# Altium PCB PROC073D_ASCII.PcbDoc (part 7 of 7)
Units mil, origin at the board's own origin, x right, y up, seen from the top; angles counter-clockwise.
Board outline 2165.35 x 2695.12 mil, 8 copper layers (Top Layer, L2_GND, L3_SIGNAL 1, L4_SIGNAL 2, L5_SIGNAL 3, L6_SIGNAL 4, L7_GND, Bottom Layer), stack 56.1 mil thick; 414 components, 319 nets, 1353 pads, 1669 vias.
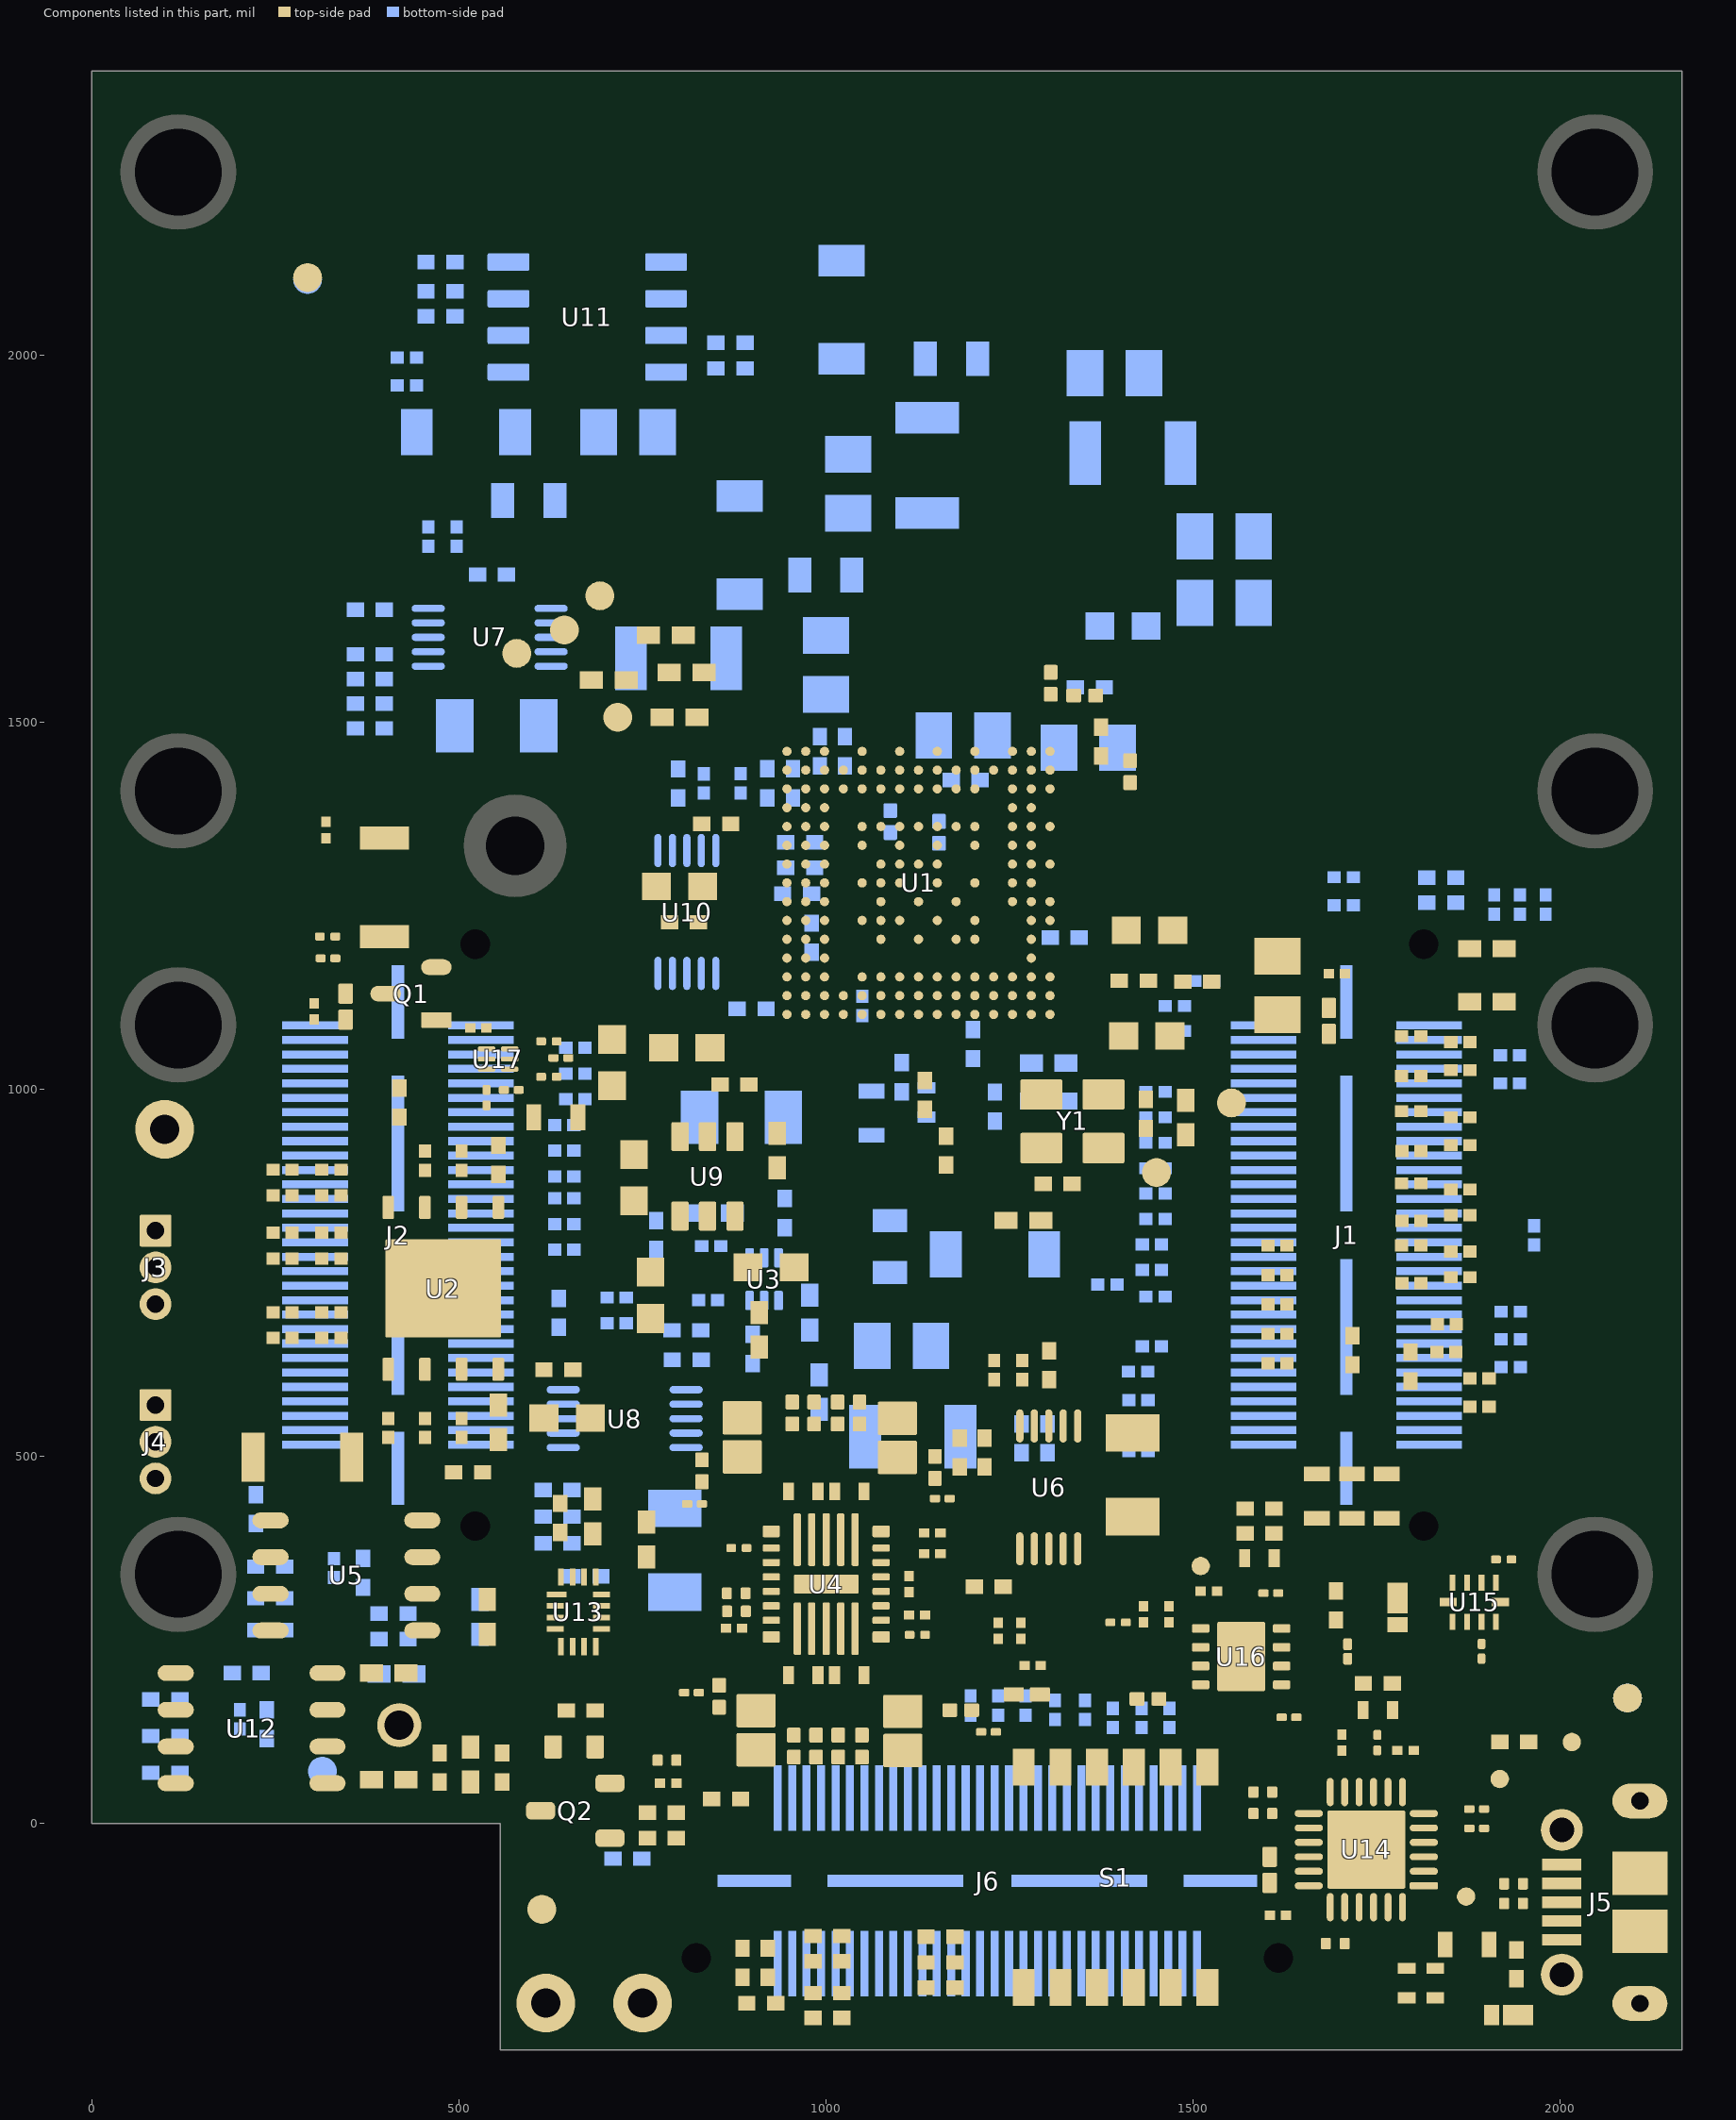
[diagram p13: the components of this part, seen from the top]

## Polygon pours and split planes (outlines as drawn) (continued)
GND on Bottom Layer "GND_L08_P43708" (solid, remove dead copper, pour order 43708): 975.14,521.11 988.65,507.61 988.65,471.77 994.8,465.62 1006.27,465.62 1025.86,485.21 1025.86,527.91 1006.22,547.55 1006.22,578.24 1002.3,582.17 980.16,582.17 975.14,577.15
GND on Bottom Layer "GND_L08_P43707" (solid, remove dead copper, pour order 43707): 1020.69,190.86 987.66,190.86 970.67,173.88 970.67,130.44 978.32,122.79 1021.07,122.79 1033.19,134.91 1033.19,178.36
VCC_3V3 on Bottom Layer "VCC_3V3_L08_P43705" (solid, remove dead copper, pour order 43705): 465.74,1033.13 458.09,1025.48 458.09,1009.78 465.84,1002.03 575.16,1002.03 575.16,1033.13
CONN_5V on Bottom Layer "CONN_5V_L08_P43704" (solid, remove dead copper, pour order 43704): 668.21,-84.13 681.85,-84.12 686.38,-79.59 686.38,-71.25 696.78,-60.85 720,-60.85 722.36,-58.49 722.36,-32.62 717.86,-28.12 689.04,-28.12 681.58,-20.66 678.03,-17.11 661.3,-17.11 655.38,-23.02 655.38,-71.3
PMIC_1V2 on Bottom Layer "PMIC_1V2_L08_P43702" (solid, remove dead copper, pour order 43702): 1134.07,211.23 1134.07,235.63 1110.26,259.43 1086.92,259.43 1076.28,248.79 1076.28,231.35 1106.13,201.5 1124.34,201.5
5V_IN on Bottom Layer "5V_IN_L08_P43699" (solid, remove dead copper, pour order 43699): 1079.81,216.18 1089.5,206.49 1095.69,200.05 1095.69,191.21 1084.57,180.09 1057.11,180.09 1051.43,185.77 1051.43,216.88 1060.25,225.7 1070.29,225.7
PMIC_1V0 on Bottom Layer "PMIC_1V0_L08_P43698" (solid, remove dead copper, pour order 43698): 876.66,448.22 876.66,420.56 896.55,400.67 911.73,400.67 919.69,408.62 919.69,420.01 899.93,439.77 899.93,445.6 889.72,455.8 884.25,455.81
PMIC_3V3 on Bottom Layer "PMIC_3V3_L08_P43701" (solid, remove dead copper, pour order 43701): 912.52,36.44 920.36,44.28 920.36,73.1 914.77,78.7 886.7,78.7 879.71,71.7 879.71,42.95 886.22,36.44
5V_IN on Bottom Layer "5V_IN_L08_P43697" (solid, remove dead copper, pour order 43697): 935.79,469.23 913.45,469.23 906.78,462.56 906.78,441.82 922.01,426.59 934.29,426.59 943.38,435.68 943.38,461.65
5V_IN on Bottom Layer "5V_IN_L08_P43696" (solid, remove dead copper, pour order 43696): 1065.52,469.88 1089.92,469.88 1094.53,465.26 1094.53,446.19 1089.35,441 1079.36,431.02 1060.29,431.02 1056.16,435.15 1056.16,460.52
5V_IN on Bottom Layer "5V_IN_L08_P43695" (solid, remove dead copper, pour order 43695): 939.63,221.08 922.83,221.08 912.64,210.9 907.24,205.5 907.24,188.9 913.3,182.84 937.84,182.84 946.5,191.5 946.5,214.21
no net on Bottom Layer "NONET_L08_P43693" (solid, remove dead copper, pour order 43693): 1569.79,-6.89
no net on Bottom Layer "NONET_L08_P43694" (solid, remove dead copper, pour order 43694): 804.19,1139.15
no net on Bottom Solder "RADAR_1V8_L01_P-001" (solid, pour order 43747): 48 vertices, not listed, extent 1068,1195.43 1955,2232.3
CONN_5V on L4_SIGNAL 2 "CONN_5V_L04_P43676" (solid, remove dead copper, pour order 43676): 22 vertices, not listed, extent 1388.84,-101.66 1860.72,535.27
VCC_LD_SW_3V3 on L4_SIGNAL 2 "VCC_LD_SW_3V3_L04_P43678" (solid, remove dead copper, pour order 43678): 826.61,990.49 837.44,979.66 930.65,979.66 990.05,920.27 990.05,583.83 942.18,535.96 942.18,502.93 925.77,486.52 865.94,486.52 813.5,538.95 713.54,538.95 706.94,545.55 706.94,982.46 714.97,990.49
GND on L4_SIGNAL 2 "GND_L04_P43683" (solid, remove dead copper, pour order 43683): 78 vertices, not listed, extent 273.62,-307.72 1388.71,1117.7
PMIC_1V2 on L4_SIGNAL 2 "PMIC_1V2_L04_P43677" (solid, remove dead copper, pour order 43677): 38 vertices, not listed, extent 678.98,78.46 1244.86,516.83
RADAR_3V3 on L4_SIGNAL 2 "RADAR_3V3_L04_P43684" (solid, remove dead copper, pour order 43684): 18 vertices, not listed, extent 788.39,1067.34 2037.57,1708.68
5V_IN on L4_SIGNAL 2 "5V_IN_L04_P43682" (solid, remove dead copper, pour order 43682): 29 vertices, not listed, extent 1546.44,-281.93 1963.86,284.3
CB_PMIC_1V0 on L4_SIGNAL 2 "CB_PMIC_1V0_L04_P43680" (solid, remove dead copper, pour order 43680): 434.47,1775.47 560.43,1775.47 647.64,1862.68 767.58,1862.68 828.79,1801.47 828.79,1543.27 721.27,1435.76 600.53,1435.76 560.34,1395.57 416.07,1395.57 400.94,1410.7 400.94,1741.94
5V_IN on L4_SIGNAL 2 "5V_IN_L04_P43681" (solid, remove dead copper, pour order 43681): 27 vertices, not listed, extent 133.29,-286.19 887.24,280.97
PMIC_1V8 on L4_SIGNAL 2 "PMIC_1V8_L04_P43679" (solid, remove dead copper, pour order 43679): 1248.09,667.01 1444.87,470.23 1444.87,387.29 1444.87,343.72 1356.02,254.87 1168.38,254.87 1037.34,385.92 980.94,385.92 948.61,418.25 948.61,533.17 992.02,576.57 992.02,636.86 1022.17,667.01
VCC_3V3 on L4_SIGNAL 2 "VCC_3V3_L04_P43675" (solid, remove dead copper, pour order 43675): 28 vertices, not listed, extent 820.26,-10.94 1308.08,317.12
RADAR_1V2 on L4_SIGNAL 2 "RADAR_1V2_L04_P43674" (solid, remove dead copper, pour order 43674): 1013.51,974.4 1116.92,974.4 1161.23,1018.71 1161.23,1052.08 1161.23,1069.81 1139.09,1091.95 985.01,1091.95 948.19,1128.77 851.6,1128.77 814.78,1091.94 814.78,1027.31 867.69,974.4
PMIC_3V3 on L4_SIGNAL 2 "PMIC_3V3_L04_P43673" (solid, remove dead copper, pour order 43673): 17 vertices, not listed, extent 845.88,35.77 958.85,254.27
CB_PMIC_1V0 on L6_SIGNAL 4 "CB_PMIC_1V0_L06_P43692" (solid, remove dead copper, pour order 43692): 23 vertices, not listed, extent 372.31,440.16 1780.59,2062.92
CONN_5V on L6_SIGNAL 4 "CONN_5V_L06_P43687" (solid, remove dead copper, pour order 43687): 23 vertices, not listed, extent 705.14,-283.5 1414.33,358.14
PMICOUT_3V3 on L6_SIGNAL 4 "PMICOUT_3V3_L06_P43689" (solid, remove dead copper, pour order 43689): 1788.28,475.23 1866.94,553.89 2079.57,553.89 2157.3,476.16 2157.3,-7.63 2057.41,-107.52 1681.52,-107.52 1635.4,-61.4 1635.4,109.01 1698.06,171.67 1788.28,261.89
5V_IN on L6_SIGNAL 4 "5V_IN_L06_P43691" (solid, remove dead copper, pour order 43691): 30 vertices, not listed, extent 29.98,-283.8 1095.63,1210.97
PMIC_1V0 on L6_SIGNAL 4 "PMIC_1V0_L06_P43690" (solid, remove dead copper, pour order 43690): 34 vertices, not listed, extent 427.96,515.02 978.35,1613.68
RADAR_1V8 on L6_SIGNAL 4 "RADAR_1V8_L06_P43688" (solid, remove dead copper, pour order 43688): 23 vertices, not listed, extent 883.8,629.93 1255.75,1534.83
PMICVIO_3V3 on L6_SIGNAL 4 "PMICVIO_3V3_L06_P43686" (solid, remove dead copper, pour order 43686): 17 vertices, not listed, extent 772.65,219.56 1190.94,488.5
VCC_3V3 on L6_SIGNAL 4 "VCC_3V3_L06_P43685" (solid, remove dead copper, pour order 43685): 347.07,1482.73 412,1417.8 412,1394.41 420.32,1386.08 420.32,1173.19 502.41,1091.11 502.41,1027.03 476.08,1000.7 376.25,1000.7 347.25,1029.7 347.25,1175.35 235.53,1287.07 235.53,1459.64 258.62,1482.73
GND on L2_GND "GND_L02_P226" (hatched 90Degree grid 5 track 8, remove dead copper, pour order 43649): 34.96,35.8 583.08,35.8 583.08,-276.77 701.29,-276.63 2135,-276.63 2135.01,2361.43 34.96,2361.42
GND on L7_GND "TOP-No Net 1" (solid, remove dead copper, pour order 43672): 0,172.07 0,39.66 28.97,10.69 544.02,10.69 575.91,-21.2 575.91,-276.57 607.69,-308.34 1082.68,-308.34 2165.35,-308.34 2165.35,2368.81 0,2368.81

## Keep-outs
L2_GND:
  circle w1: c1074.8,1434.59 r7.87
  circle w1: c1177.16,1434.59 r7.87
  circle w1: c1125.98,1434.59 r7.87
  circle w1: c1279.53,1281.05 r7.87
  circle w1: c1279.52,1383.41 r7.87
  circle w1: c1279.52,1332.23 r7.87
  circle w1: c522.48,1197.95 r32
  circle w1: c1023.62,1434.59 r7.87
L3_SIGNAL 1:
  circle w1: c522.48,1197.95 r32
L5_SIGNAL 3:
  circle w1: c522.48,1197.95 r30
L7_GND:
  circle w1: c522.48,1196.95 r32
Bottom Layer:
  circle w1: c522.48,1197.95 r27.7
Keep-Out Layer:
  circle w1: c823.48,-182.98 r32
  circle w1: c1616,-182.98 r32
  circle w1: c522.48,1197.43 r32
  circle w1: c1813.86,1197.69 r32
  circle w1: c1813.86,405.17 r31
  circle w1: c522.48,404.91 r32
  lines w10: -5,-5 551.54,-5 551.54,-313.34 2170.35,-313.34 2170.35,2391.78 -5,2391.78 -5,-5
  text ".Layer_Name" at -423,-1637.06 h60

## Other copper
Top Layer:
  text ".Layer_Name" at -423,-1637.06 h60
L2_GND:
  text ".Layer_Name" at -423,-1637.06 h60
L3_SIGNAL 1:
  text ".Layer_Name" at -423,-1637.06 h60
L5_SIGNAL 3:
  text ".Layer_Name" at -423,-1637.06 h60
L7_GND:
  text ".Layer_Name" at -423,-1637.06 h60
L4_SIGNAL 2:
  text ".Layer_Name" at -423,-1637.06 h60
L6_SIGNAL 4:
  text ".Layer_Name" at -423,-1637.06 h60
Bottom Layer:
  text ".Layer_Name" at -423,-1637.06 h60

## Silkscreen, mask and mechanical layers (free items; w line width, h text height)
Top Overlay:
  circle w6: c486.63,1402.09 r30
  circle w10: c1851.26,-90.22 r4.23
  rectangle: 1334.64,1437.44 1353.4,1473.8
  lines w6: 187.08,648.37 187.08,663.46 216.47,692.85 ; 203.5,897.76 198.92,893.18 198.92,786.66 214.76,770.82 ; 359.1,630.7 371.21,642.81 371.21,683.3 364.91,689.6 ; 479.38,497.57 497.97,497.57 500.7,500.3 ; 627.98,1907.74 627.98,1754.26 696.21,1754.26 ; 648.31,1016.63 654.42,1016.63 664.22,1026.43 664.22,1159.01 ; 657.67,-196.22 706.66,-147.23 ; 713.82,1771.85 713.82,1906.52 ; 726.18,1864.99 731.82,1859.36 731.82,1665.75 746.37,1651.2 ; 895.08,-55.65 923.22,-83.79 923.22,-145.7 ; 1024.91,-22.27 1033.92,-31.29 1033.92,-132.02 ; 1073.36,200.77 1098.69,200.77 1106.54,208.62 ; 1151.44,-53.19 1173.87,-75.62 1173.87,-132.25 ; 1164.06,461.56 1194.56,461.56 ; 1432.01,927.8 1432.01,910.65 1398.09,876.73 ; 1432.32,236.29 1432.32,257.47 ; 1460.96,324.94 1464.36,321.55 1464.36,313.48 ; 1486.06,380.76 1486.06,342.13 1491.66,336.53 ; 1552.22,441.76 1552.22,357.83 1555.67,354.37 ; 1622.2,14.4 1630.02,22.22 1630.02,38.52 ; 1636.74,-105.56 1651.26,-120.08 1651.26,-206.52 1647.26,-210.52 ; 1742.66,1043.42 1742.66,1048.18 1754.79,1060.31 ; 1750.24,-194.69 1765.99,-178.94 1810.5,-178.94 1813.92,-182.36 ; 1398.09,876.73 1408.09,876.73 1398.09,886.73 1398.09,876.73
  text "PROC073    REV D" at 498.37,1516.31 h45 r90
  text "C" at 1267.07,1500.27 h50
  text "C" at 473.15,1386 h50
  text ".Layer_Name" at -423,-1637.06 h60
Bottom Overlay:
  circle w6: c1519.56,1949.66 r30
  circle w6: c696.91,1476.87 r30
  circle w6: c667.74,1135.94 r30
  circle w6: c306.34,2022.03 r30
  lines w6: 190.46,462.35 196.84,455.97 196.84,388.99 210.64,375.18 ; 230.93,1048.86 249.25,1067.18 ; 260.27,1681.28 367.53,1681.28 367.53,1974.51 ; 603.52,363 603.52,211.13 609.81,204.84 ; 618.56,758.7 677.15,758.7 677.71,759.26 677.71,954.38 698.6,975.27 698.6,1081.8 638.79,1081.8 ; 722.34,1454.6 734.1,1442.84 775.46,1442.84 ; 779.7,1385.25 779.7,1456.44 931.48,1456.44 966.88,1491.84 975.56,1491.84 ; 849.15,668.59 869.41,648.34 869.41,604.48 ; 911.78,1303.56 925.28,1303.56 ; 915.72,796.02 915.72,863.46 ; 997.88,1408.3 1062.42,1408.3 1073.68,1419.57 1073.68,1469.29 1050.83,1492.14 1047.37,1492.14 ; 1457.62,2032.88 1457.62,2102.66 1701.27,2102.66 1701.27,2021.45 1701.27,1988.75 1590.42,1988.75 ; 1864.28,1231.5 1864.28,1223.35 1900.82,1186.81 ; 1872.86,515.65 1888.58,499.93 1888.54,457.99
  text "A" at 323.27,2006.33 h50
  text "B" at 1531.31,1932.8 h50
  text "B" at 708.67,1460 h50
  text "5V_IN" at 480.84,1240.74 h45
  text "A" at 684.67,1120.24 h50
  text "60" at 1938.04,1117.62 h60
  text "5V_IN" at 220.8,1086.19 h50 r270
  text "VPP_1P7" at 219.08,892.8 h40 r270
  text "1V8" at 1546.29,581.12 h40
  text "1V2" at 1546.95,549.97 h40
  text "3V3" at 1939.64,530.67 h40
  text "1V0" at 1544.85,512.29 h40
  text "2" at 589.41,507.23 h40
  text "1" at 228.35,497.9 h40
  text "5V_IN" at 1957.22,422.23 h40
  text "1" at 1549.43,389.07 h60
  text "TEXAS" at 1484.42,350.58 h70
  text "INSTRUMENTS" at 1583.13,294.25 h70
  text ".Layer_Name" at -423,-1637.06 h60
Top Paste:
  text ".Layer_Name" at -423,-1637.06 h60
Bottom Paste:
  text ".Layer_Name" at -423,-1637.06 h60
Top Solder:
  rectangle: 33,2226.43 1975.16,2365.43
  text ".Layer_Name" at -423,-1637.06 h60
  text ".Layer_Name" at -423,-1637.06 h60
Bottom Solder:
  text ".Layer_Name" at -423,-1637.06 h60
Drill Guide:
  text ".Layer_Name" at -423,-1637.06 h60
M1 Board Outline:
  the board outline again, w10
  text ".Layer_Name" at -423,-1637.06 h60
M2 Board Dimensions:
  rectangle: -1000,-1053.57 -875,-928.57
  rectangle: -875,-1178.57 -500,-1053.57
  lines w7: -1000,-1053.57 0,-1053.57 ; -875,-1178.57 -875,-928.57 ; -750,-1178.57 -750,-928.57 ; -500,-1178.57 -500,-928.57 ; -250,-1178.57 -250,-928.57 ; -1000,-1178.57 0,-1178.57 0,-928.57 -1000,-928.57 -1000,-1178.57
  text ".Layer_Name" at -434.88,-1635.12 h60
M3 3D STEP Top:
  text ".Layer_Name" at -423,-1637.06 h60
M4 3D STEP Bottom:
  text ".Layer_Name" at -423,-1637.06 h60
M5 Assembly Top:
  lines w10: -1292,-1708.74 5308,-1708.74 ; -1292,-1505.4 5310,-1505.4 ; -1292,-1302.07 -1292,-1912.07 2713,-1912.07 5310,-1912.07 5310,-1302.07 -1291.5,-1302.07 -1291.5,-1912.07 284,-1912.07 ; 1173,-1912.07 1173,-1302.07 ; 2440,-1505.4 2440,-1302.07 ; 3280,-1505.4 3280,-1302.07 ; 3902,-1918.57 3902,-1715.74
  text "COMPONENTS MARKED 'DNP' SHOULD NOT BE POPULATED." at 153.5,-1097.07 h60
  text "ASSEMBLY VARIANT:" at 153,-1212.57 h60
  text ".VariantName" at 1189,-1212.57 h60
  text "PCB VIEWED FROM TOP SIDE" at -1228.5,-1434.24 h60
  text "BOARD #:" at 1248,-1434.24 h60
  text ".PRJ_Number" at 1793.5,-1434.24 h60
  text "REV:" at 2638,-1434.24 h60
  text ".PCB_Rev" at 2929.5,-1434.24 h60
  text "SVN REV:" at 3476,-1434.24 h60
  text ".VersionControl_RevNumber" at 3982,-1434.24 h60
  text "Assembly Layer Top" at -433,-1633.57 h60
  text "TID #:" at 1248,-1637.57 h60
  text ".TID" at 1793.5,-1637.57 h60
  text "PLOT NAME =" at -1228.5,-1842.91 h60
  text ".plot_File_Name" at -423,-1842.91 h60
  text "GENERATED    :" at 1250,-1842.91 h60
  text ".Print_Date" at 2119.5,-1842.91 h60
  text ".Print_Time" at 2848.5,-1842.91 h60
  text "TEXAS INSTRUMENTS" at 4113,-1842.91 h60
M6 Assembly Bottom:
  lines w6: 705,946.43 705,1086.43 ; 786.98,859.14 791.01,855.11 791.01,805.11 810.46,785.66 810.46,792.86 802.41,784.81 809.61,784.81 ; 833.84,1452.2 833.84,1469.69 ; 1770.26,1355.04 1770.26,1297.39 1798.64,1269 1798.64,1278.88 1788.68,1268.91 1796.09,1268.91 ; 705,1086.43 714.25,1077.18 695.75,1077.18 705,1086.43
  lines w10: -1292.5,-1505.9 5309.5,-1505.9 ; -1290.5,-1709.24 5309.5,-1709.24 ; 115.5,-1919.07 115.5,-1716.24 ; 737.5,-1505.9 737.5,-1302.57 ; 1577.5,-1505.9 1577.5,-1302.57 ; 2844.5,-1912.57 2844.5,-1302.57 ; 3733.5,-1912.57 5309,-1912.57 5309,-1302.57 -1292.5,-1302.57 -1292.5,-1912.57 1304.5,-1912.57 5309.5,-1912.57 5309.5,-1302.57
  text "59" at 350,1086.43 h45
  text "60" at 530.04,1086.86 h45
  text "59" at 1636,1086.86 h45
  text "60" at 1821.54,1086.86 h45
  text "1" at 325,496.43 h45
  text "2" at 525,496.43 h45
  text "1" at 1611,486.43 h45
  text "2" at 1822,486.43 h45
  text "COMPONENTS MARKED 'DNP' SHOULD NOT BE POPULATED." at 5102,-1096.57 h60
  text ".VariantName" at 4058,-1212.57 h60
  text "ASSEMBLY VARIANT:" at 5097,-1212.57 h60
  text ".VersionControl_RevNumber" at 35.5,-1434.74 h60
  text "SVN REV:" at 541.5,-1434.74 h60
  text ".PCB_Rev" at 1088,-1434.74 h60
  text "REV:" at 1379.5,-1434.74 h60
  text ".PRJ_Number" at 2224,-1434.74 h60
  text "BOARD #:" at 2769.5,-1434.74 h60
  text "PCB VIEWED FROM BOTTOM SIDE" at 5246,-1434.74 h60
  text "Assembly Bottom Layer" at 4885,-1623.57 h60
  text ".TID" at 2224,-1638.07 h60
  text "TID #:" at 2769.5,-1638.07 h60
  text "TEXAS INSTRUMENTS" at -95.5,-1843.41 h60
  text ".Print_Time" at 1169,-1843.41 h60
  text ".Print_Date" at 1898,-1843.41 h60
  text "GENERATED    :" at 2767.5,-1843.41 h60
  text ".plot_File_Name" at 4440.5,-1843.41 h60
  text "PLOT NAME =" at 5246,-1843.41 h60
M7 LPKF Text Top:
  lines w2: 1007.88,1434.59 1039.36,1434.59 ; 1015.75,1434.59 1031.49,1434.59 ; 1023.62,1418.85 1023.62,1450.33 ; 1023.62,1426.72 1023.62,1442.46
M9 Title Sheet:
  lines w10: -1491.5,262.93 -1291.5,262.93 ; -1491.5,2637.93 -1291.5,2637.93 ; -1491.5,5012.93 -1291.5,5012.93 ; 1008.5,-2112.07 1008.5,-1912.07 ; 1008.5,7187.93 1008.5,7387.93 ; 3508.5,-2112.07 3508.5,-1912.07 ; 3508.5,7187.93 3508.5,7387.93 ; 5321,-1912.07 5321,-1302.07 10303.5,-1302.07 ; 6008.5,-2112.07 6008.5,-1912.07 ; 6008.5,7187.93 6008.5,7387.93 ; 8508.5,-2112.07 8508.5,-1912.07 ; 8508.5,7187.93 8508.5,7387.93 ; 10303.5,-1912.07 10303.5,-1302.07 ; 10303.5,-1602.07 13303.5,-1602.07 ; 10303.5,-1002.07 13303.5,-1002.07 ; 10304.5,-408.07 13304.5,-408.07 ; 11008.5,-2112.07 11008.5,-1912.07 ; 11008.5,7187.93 11008.5,7387.93 ; 11808.5,-1902.07 11808.5,-1302.07 ; 13303.5,-1302.07 10303.5,-1302.07 ; 13303.5,-702.07 10303.5,-702.07 ; 13308.5,-712.07 13308.5,-1912.07 ; 13308.5,92.43 10304.5,92.43 10303.5,92.43 10303.5,-408.07 10303.5,-702.07 ; 13308.5,262.93 13508.5,262.93 ; 13308.5,2637.93 13508.5,2637.93 ; 13308.5,5012.93 13508.5,5012.93 ; 10303.5,-1302.07 10303.5,-702.07 ; 13308.5,-1912.07 13308.5,7187.93 -1291.5,7187.93 -1291.5,-1912.07 13308.5,-1912.07 ; -1491.5,-2112.07 -1491.5,7387.93 13508.5,7387.93 13508.5,-2112.07 -1491.5,-2112.07
  text "1" at -260.16,7257.93 h70
  text "2" at 2235.5,7257.93 h70
  text "3" at 4724.84,7257.93 h70
  text "4" at 7231.51,7257.93 h70
  text "5" at 9730.5,7257.93 h70
  text "6" at 12235.5,7257.93 h70
  text "A" at -1416.5,6114.93 h70
  text "A" at 13383.5,6114.93 h70
  text "B" at -1416.5,3734.93 h70
  text "B" at 13383.5,3734.93 h70
  text "C" at -1416.5,1359.93 h70
  text "C" at 13383.5,1359.93 h70
  text "PROJECT TITLE:" at 10343.5,-501.07 h45
  text ".PRJ_Title" at 10393.5,-634.4 h70
  text "DESIGNED FOR:" at 10343.5,-802.07 h45
  text ".PRJ_Customer" at 10393.5,-942.07 h70
  text "D" at -1416.5,-1010.07 h70
  text "D" at 13383.5,-1010.07 h70
  text "FILE NAME:" at 10343.5,-1102.07 h45
  text ".PCB_File_Name_No_Path" at 10393.5,-1222.07 h70
  text "Texas Instruments (TI) and/or its licensors do not warrant the accuracy or completeness of this specification" at 5374,-1383.91 h45
  text "ENGINEER:" at 10343.5,-1392.07 h45
  text "LAYOUT BY:" at 11848.5,-1392.07 h45
  text "or any information contained therein. TI and/or its licensors do not warrant that this design will meet" at 5329.01,-1496.57 h45
  text ".PRJ_Engineer" at 10393.5,-1547.06 h70
  text ".PCB_Layout" at 11899,-1547.06 h70
  text "the specifications, will be suitable for your application or fit for any particular purpose, or will operate in" at 5329.01,-1609.24 h45
  text ".Layer_Name" at -413.7,-1644.05 h60
  text "ALTIUM DESIGNER VERSION:" at 11848.5,-1702.07 h45
  text "an implementation. TI and/or its licensors do not warrant that the design is production worthy. You should" at 5329.01,-1721.91 h45
  text "completely validate and test your design implementation to confirm the system functionality for your application." at 5374,-1834.57 h45
  text ".print_Scale" at 10393.5,-1835.4 h70
  text ".Application_BuildNumber" at 11899,-1835.4 h70
  text "1" at -260.16,-2042.07 h70
  text "2" at 2235.5,-2042.07 h70
  text "3" at 4724.84,-2042.07 h70
  text "4" at 7231.51,-2042.07 h70
  text "5" at 9730.5,-2042.07 h70
  text "WO # : 308145-8143-D" at 12235.5,-2042.07 h70
M10 Fab Notes:
  drawing of 198 lines, arcs and shapes, not listed
  text "DESIGN INFORMATION" at 11382.02,5577.6 h60
  text "MIN. TRACK WIDTH:" at 10737.46,5445.48 h60
  text "4" at 11833.7,5445.48 h60
  text "MIL" at 11988.46,5445.48 h60
  text "3.9" at 11781.69,5328.63 h60
  text "MIN. CLEARANCE:" at 10737.46,5321.35 h60
  text "MIL" at 11988.46,5321.35 h60
  text "MIN. VIA PAD SIZE:" at 10737.46,5197.23 h60
  text "13.77" at 11679,5192.43 h60
  text "MIL" at 12011,5188.43 h60
  text "EXTERNAL" at 12258.6,5069.92 h60
  text "0.0508mm (2.0MIL)" at 11432.46,5067.33 h60
  text "MINIMUM ANNULAR RING" at 10408.23,5059.1 h60
  text "PER" at 10608.23,4948.98 h60
  text "IPC-D-275 CLASS 2 LEVEL C" at 10828.23,4948.97 h60
  text "MIL, HOLES" at 12316.46,4848.5 h60
  text "+/-" at 11924,4839.91 h60
  text "+/-" at 12778,4839.91 h60
  text "REGISTRATION TOLERANCES:" at 10408.23,4838.85 h60
  text "METAL" at 11608,4838.85 h60
  text "5" at 12184.2,4838.85 h60
  text "3" at 13017.2,4838.85 h60
  text "MIL" at 13133.46,4838.85 h60
  text "HOLE SIZE TOLERANCE (UNLESS OTHERWISE SPECIFIED):" at 10408.23,4740.53 h60
  text "+/-" at 12778,4737.66 h60
  text "3" at 13017.2,4736.6 h60
  text "MIL" at 13133.46,4736.6 h60
  text "MATERIAL:" at 10333.46,4598.95 h60
  text "FR-4 High Tg" at 11319.9,4470.42 h60
  text "X" at 12062,4465.43 h60
  text "REFER STACK-UP" at 12562.85,4464.84 h55
  text "FR-408" at 10754.46,4457.92 h60
  text "OTHER" at 12242.46,4457.92 h60
  text "X" at 12233,4317.44 h60
  text "62 MIL (1.6mm) +/-10%" at 11074.56,4314.89 h60
  text "57.37 MIL +/-10%" at 12655,4308.43 h45
  text "THICKNESS:" at 10408.23,4306.67 h60
  text "OTHER" at 12359.46,4306.67 h60
  text "TOLERANCE:" at 10408.23,4168.35 h60
  text "X" at 11256.46,4168.35 h60
  text "ANSI IPC-6012 TYPE 3 CLASS 2" at 11434.48,4168.35 h60
  text "OTHER +/-" at 11434.46,4024.16 h60
  text "BOW & TWIST:" at 10408.23,3878.97 h60
  text "X" at 11256.46,3878.97 h60
  text "ANSI IPC-6012 TYPE 3 CLASS 2" at 11434.48,3878.97 h60
  text "OTHER +/-" at 11434.46,3732.28 h60
  text "DRILLING:" at 10333.46,3601.66 h60
  text "NC_DRILL FILES" at 12094.46,3496.47 h60
  text "REFERENCE:" at 10408.23,3492.53 h60
  text "X" at 11065.46,3492.44 h60
  text "AS SHOWN" at 11243.46,3492.53 h60
  text "X" at 11966.46,3492.53 h60
  text "OTHER" at 12392.46,3350.28 h60
  text "PTH COPPER THICKNESS:" at 10407.91,3346.75 h60
  text "X" at 11547.14,3346.75 h60
  text "20-30 um" at 11675.14,3346.75 h60
  text "BOARD FINISH:" at 10333.46,3199.15 h60
  text "SILKSCREEN:" at 10488.68,3089.03 h60
  text "X" at 11446.46,3089.03 h60
  text "TOP" at 11563.46,3089.03 h60
  text "X" at 11956.46,3089.03 h60
  text "BOTTOM" at 12074.46,3089.03 h60
  text "SILKSCREEN COLOR:" at 10488.68,2933.84 h60
  text "X" at 11445.46,2933.84 h60
  text "WHITE" at 11563.46,2933.84 h60
  text "OTHER" at 12074.46,2933.84 h60
  text "GREEN" at 11694.46,2790.39 h60
  text "X" at 12168.46,2790.39 h60
  text "OTHER" at 12312.46,2790.39 h60
  text "RED" at 12685,2790.39 h60
  text "SOLDER RESIST COLOR:" at 10488.68,2783.52 h60
  text "MATTE" at 11694.46,2636.14 h60
  text "SEMI-GLOSS" at 12312,2635.5 h60
  text "X" at 12168.06,2633.44 h60
  text "IMMERSION GOLD (ENIG)" at 11394.46,2463.37 h60
  text "ENEPIG" at 12732,2456.15 h60
  text "SURFACE FINISH:" at 10333.46,2455.15 h60
  text "IMM. TIN/SILVER OR EQUIV" at 10663,2317.83 h60
  text "X" at 10510,2315.15 h60
  text "OTHER" at 12094.46,2313.89 h60
  text "NOTES:" at 3534.49,2188.99 h60
  text "ARRAY/PANEL:" at 10333.46,2158.52 h60
  text "CUT AND TRIM PER M1 BOARD OUTLINE" at 11394.46,2150.29 h60
  text "N.C. ROUTE" at 11394.46,2014.33 h60
  text "X" at 12082.46,2014.33 h60
  text "V. SCORE" at 12260.46,2014.33 h60
  text "1. VIA'S ON PAD AND BGA PACKAGE AREA SHOULD BE FILLED WITH CONDUCTIVE MATERIAL AND SURFACE SHOULD BE FLAT" at 3563.63,2013.82 h60
  text "BGA AREA VIAS SHOULD BE CAPPED WITH COPPER PLATING TO ENSURE FLAT SURFACE" at 3670.36,1906.67 h60
  text "CERTIFICATION:" at 10333.46,1885.2 h60
  text "MATERIALS AND WORKMANSHIP FOR ALL PCBS" at 11058.46,1885.2 h60
  text "FLATNESS TOLERANCE FOR VIA ON PADS: +0.000 /- 0.001 INCHES ON BOTH SIDES." at 3670.36,1808.09 h60
  text "TO MEET OR EXCEED THE REQUIREMENTS OF:" at 11058.46,1791.14 h60
  text "OTHER THAN BGA AND VIA'S ON THE PAD  VIA FILLING REQUIREMENT CAN BE EXEMPTED" at 3670.36,1698.08 h60
  text "X" at 10695.97,1662.51 h60
  text "ANSI IPC-A-600F CLASS ->" at 10823.96,1662.51 h60
  text "X" at 12471.97,1662.51 h60
  text "2" at 12581.96,1662.51 h60
  text "1" at 12266.96,1661.01 h60
  text "3" at 12935.96,1661.01 h60
  text "2. VENDOR MAY ADJUST SOLDERMASK WHEREVER SOLDERMASK PADS ARE THE SAME SIZE (1:1) AS PER THE MANUFACTURING CAPABILITIES" at 3563.63,1570.41 h60
  text "X" at 11507.97,1514.82 h60
  text "RoHS" at 11635.96,1514.82 h60
  text "OTHER" at 12280.36,1514.82 h60
  text "PER ORDER" at 12677.42,1514.82 h60
  text "AND ALL OTHER SOLDER MASK PADS SHALL NOT BE MODIFIED, PROVIDED NO ADJACENT COPPER IS EXPOSED AND NO CONFLICT IS PRODUCED" at 3670.36,1471.41 h60
  text "WITH ANY STATED \"VIA TENTING/COVERING\" REQUIREMENTS." at 3670.36,1378.13 h60
  text "ALL BOARDS MUST MEET OR EXCEED UL94-V0 REQUIREMENTS." at 10361,1361 h60
  text "PCB MUST BEAR THE UL94V-0 UL REGISTERED MATERIAL ID NUMBER" at 10361,1244.93 h60
  text "3. MANUFACTURER'S IDENTIFICATION,DATECODE LETTER SHALL BE SILKSCREENED ON SOLDER SIDE OF THE BOARD." at 3563.63,1217.04 h60
  text "ADDITIONAL REQUIREMENTS:" at 10333.46,1075.51 h60
  text "4. TRACE WIDTH SHOULD BE ACCURATELY ETCHED. MAX TOLERANCE +/- 1 MIL." at 3563.63,1066.86 h60
  text "MICROSECTION:" at 10408.23,968.38 h60
  text "YES" at 11313.96,968.38 h60
  text "5. LAYER TO LAYER REGISTRATION SHALL BE WITHIN +/-2 MIL." at 3563.63,919.55 h60
  text "REQUIRED" at 12175.46,824.05 h60
  text "BARE BOARD ELEC. TEST:" at 10408.23,821.19 h60
  text "NONE" at 11713.96,821.19 h60
  text "X" at 12057.46,821.19 h60
  text "PER ORDER" at 12767.46,821.19 h60
  text "6. REFER IMPEDANCE TABLE FOR IMPEDANCE CONTROL TRACES ON LAYER 1, 3, 6 & 8." at 3563.63,775.09 h60
  text "XX MIL VIAS REQUIRE NON-CONDUCTIVE FILL AND PLANARIZE" at 10592,675.43 h59
  text "7. FOR ACCURACY OF THE ANTENNA DIMENSION, NEED TO BE MEASURE THE  ANTENNA DIMENSIONS ON ONE BAORD" at 3563.63,627.77 h60
  text "XX MIL VIAS REQUIRE CONDUCTIVE FILL AND PLANARIZE" at 10583,516.43 h60
  text "AS PER  ANTENNA DOCUMENT( Visio-IWR_60GHz4)." at 3670.36,507.35 h60
  text "OUTER XX MIL TRACES REQUIRE 50 OHM SINGLE-ENDED IMPEDANCE" at 10578.15,373.53 h58
  text "8. ALL VIAS ARE TENTED ON BOTH SIDES UNLESS OTHERWISE SOLDER MASK OPENED IN GERBER." at 3563.63,351.89 h60
  text "9. INTENTIONAL ONE NET ANTENNA VIA IS PRESENT IN DESIGN." at 3563.63,180.37 h60
  text "LAYER 1 & 6 (INNER LAYERS) XX MIL WIDE, XX MIL SPACE / TRACES REQUIRE 100 OHM DIFFERENTIAL IMPEDANCE" at 10617,123.43 h60
  text ".Layer_Name" at -425.59,-1637.69 h60
M11 Gerber Information:
  lines w10: -1292,-1708.74 5308,-1708.74 ; -1292,-1505.4 5310,-1505.4 ; -1292,-1302.07 -1292,-1912.07 2713,-1912.07 5310,-1912.07 5310,-1302.07 -1291.5,-1302.07 -1291.5,-1912.07 284,-1912.07 ; 1173,-1912.07 1173,-1302.07 ; 2440,-1505.4 2440,-1302.07 ; 3280,-1505.4 3280,-1302.07 ; 3902,-1918.57 3902,-1715.74
  text "ALL ARTWORK VIEWED FROM TOP SIDE" at -1228.5,-1434.24 h60
  text "BOARD #:" at 1248,-1434.24 h60
  text ".PRJ_Number" at 1793.5,-1434.24 h60
  text "REV:" at 2638,-1434.24 h60
  text ".PCB_Rev" at 2929.5,-1434.24 h60
  text "SVN REV:" at 3476,-1434.24 h60
  text ".VersionControl_RevNumber" at 3982,-1434.24 h60
  text "LAYER NAME =" at -1228.5,-1637.06 h60
  text "TID #:" at 1248,-1637.57 h60
  text ".TID" at 1793.5,-1637.57 h60
  text "PLOT NAME =" at -1228.5,-1842.91 h60
  text ".plot_File_Name" at -423,-1842.91 h60
  text "GENERATED    :" at 1250,-1842.91 h60
  text ".Print_Date" at 2119.5,-1842.91 h60
  text ".Print_Time" at 2848.5,-1842.91 h60
  text "TEXAS INSTRUMENTS" at 4113,-1842.91 h60
M12 Stackup:
  drawing of 562 lines, arcs and shapes, not listed
  text "LAYER STACK-UP :" at 5193.51,6770.46 h80
  text "Layer" at 5213.17,6600.19 h60
  text "Name" at 5623.08,6600.19 h60
  text "Material" at 6552.82,6600.19 h60
  text "Thickness" at 7412.59,6600.19 h60
  text "Constant" at 8062.42,6600.19 h60
  text "Board Layer Stack" at 8632.29,6600.19 h60
  text "1" at 5213.17,6480.19 h60
  text "Top Overlay" at 5623.08,6480.19 h60
  text "2" at 5213.17,6360.19 h60
  text "Top Solder" at 5623.08,6360.19 h60
  text "Solder Resist" at 6552.82,6360.19 h60
  text "0.80mil" at 7412.59,6360.19 h60
  text "1" at 8062.42,6360.19 h60
  text "6" at 5023.59,6241.31 h60
  text "3" at 5213.17,6240.19 h60
  text "Top Layer" at 5623.08,6240.19 h60
  text "Copper" at 6552.82,6240.19 h60
  text "1.60mil" at 7412.59,6240.19 h60
  text "4" at 5213.17,6120.19 h60
  text "Dielectric 1" at 5623.08,6120.19 h60
  text "RO4835 LOPRO" at 6552.82,6120.19 h60
  text "4.00mil" at 7412.59,6120.19 h60
  text "3.5" at 8062.42,6120.19 h60
  text "5" at 5213.17,6000.19 h60
  text "L2_GND" at 5623.08,6000.19 h60
  text "Copper" at 6552.82,6000.19 h60
  text "1.40mil" at 7412.59,6000.19 h60
  text "6" at 5213.17,5880.19 h60
  text "Dielectric 2" at 5623.08,5880.19 h60
  text "PCL370HR" at 6552.82,5880.19 h60
  text "5.50mil" at 7412.59,5880.19 h60
  text "4.17" at 8062.42,5880.19 h60
  text "6" at 5019.85,5763.04 h60
  text "7" at 5213.17,5760.19 h60
  text "L3_SIGNAL 1" at 5623.08,5760.19 h60
  text "Copper" at 6552.82,5760.19 h60
  text "1.40mil" at 7412.59,5760.19 h60
  text "8" at 5213.17,5640.19 h60
  text "Dielectric 3" at 5623.08,5640.19 h60
  text "PCL370HR" at 6552.82,5640.19 h60
  text "10.00mil" at 7412.59,5640.19 h60
  text "4.17" at 8062.42,5640.19 h60
  text "9" at 5213.17,5520.19 h60
  text "L4_SIGNAL 2" at 5623.08,5520.19 h60
  text "Copper" at 6552.82,5520.19 h60
  text "1.40mil" at 7412.59,5520.19 h60
  text "10" at 5213.17,5400.19 h60
  text "Dielectric 4" at 5623.08,5400.19 h60
  text "PCL370HR" at 6552.82,5400.19 h60
  text "5.50mil" at 7412.59,5400.19 h60
  text "4.17" at 8062.42,5400.19 h60
  text "11" at 5213.17,5280.19 h60
  text "L5_SIGNAL 3" at 5623.08,5280.19 h60
  text "Copper" at 6552.82,5280.19 h60
  text "1.40mil" at 7412.59,5280.19 h60
  text "12" at 5213.17,5160.19 h60
  text "Dielectric 5" at 5623.08,5160.19 h60
  text "PCL370HR" at 6552.82,5160.19 h60
  text "10.00mil" at 7412.59,5160.19 h60
  text "4.17" at 8062.42,5160.19 h60
  text "13" at 5213.17,5040.19 h60
  text "L6_SIGNAL 4" at 5623.08,5040.19 h60
  text "Copper" at 6552.82,5040.19 h60
  text "1.40mil" at 7412.59,5040.19 h60
  text "6" at 5022.17,5037.34 h60
  text "14" at 5213.17,4920.19 h60
  text "Dielectric 6" at 5623.08,4920.19 h60
  text "PCL370HR" at 6552.82,4920.19 h60
  text "5.50mil" at 7412.59,4920.19 h60
  text "4.17" at 8062.42,4920.19 h60
  text "15" at 5213.17,4800.19 h60
  text "L7_GND" at 5623.08,4800.19 h60
  text "Copper" at 6552.82,4800.19 h60
  text "1.40mil" at 7412.59,4800.19 h60
  text "16" at 5213.17,4680.19 h60
  text "Dielectric 7" at 5623.08,4680.19 h60
  text "PCL370HR" at 6552.82,4680.19 h60
  text "4.00mil" at 7412.59,4680.19 h60
  text "4.17" at 8062.42,4680.19 h60
  text "17" at 5213.17,4560.19 h60
  text "Bottom Layer" at 5623.08,4560.19 h60
  text "Copper" at 6552.82,4560.19 h60
  text "1.60mil" at 7412.59,4560.19 h60
  text "6" at 5025.35,4557.75 h60
  text "18" at 5213.17,4440.19 h60
  text "Bottom Solder" at 5623.08,4440.19 h60
  text "Solder Resist" at 6552.82,4440.19 h60
  text "0.80mil" at 7412.59,4440.19 h60
  text "1" at 8062.42,4440.19 h60
  text "19" at 5213.17,4320.19 h60
  text "Bottom Overlay" at 5623.08,4320.19 h60
  text "NOTE :" at 5225.04,4170.48 h60
  text "1. THIS IS AN IMPEDANCE CONTROLLED BOARD." at 5408.55,4065.46 h60
  text "2. EXTERNAL LAYER CU THICKNESSES ARE FINISHED THICKNESS AFTER PLATING." at 5408.55,3967.59 h60
  text "6" at 7261.89,3747.14 h60
  text "IMPEDANCE TABLE :" at 6105.5,3731.76 h80
  text "SPACING" at 6299.43,3576.01 h70
  text "LAYER" at 5549.43,3571.01 h70
  text "TRACE WIDTH" at 5814.43,3571.01 h70
  text "IMPEDANCE +/- 10%" at 6634.43,3571.01 h70
  text "REFERENCE LAYER" at 7359.43,3571.01 h70
  text "TOP" at 5584.43,3421.01 h70
  text "7.795 MILS" at 5869.43,3416.01 h65
  text "8 MILS" at 6324.43,3416.01 h65
  text "50 OHM" at 6744.43,3416.01 h65
  text "LAYER-2 (GND LAYER)" at 7309.43,3416.01 h65
  text "LAYER" at 5564.57,3201.93 h70
  text "TRACE WIDTH" at 5851.77,3201.09 h70
  text "SPACING" at 6336.77,3201.09 h70
  text "IMPEDANCE +/- 10%" at 6671.77,3201.09 h70
  text "REFERENCE LAYER" at 7396.77,3201.09 h70
  text "LAYER-2 AND" at 7510.74,3061.09 h65
  text "TOP AND" at 5529.48,3057.24 h70
  text "5.2 MILS" at 5952.73,3041.09 h65
  text "5 MILS" at 6385.52,3041.09 h65
  text "100 OHM" at 6853.75,3041.09 h65
  text "BOTTOM" at 5555.85,2988.55 h60
  text "LAYER-7" at 7581.18,2986.09 h65
  text "LAYER-2, LAYER 4 &" at 7412.84,2884.41 h65
  text "4.8 MILS" at 5951.98,2851.18 h65
  text "7.2 MIL" at 6380.02,2851.18 h65
  text "100 OHM" at 6853.75,2851.18 h65
  text "L3 & L6" at 5558.48,2849.72 h70
  text "LAYER-5, LAYER 7" at 7442.71,2814.02 h65
  text ".Layer_Name" at -423,-1637.06 h60
M13 Component Bodies Top:
  text ".Layer_Name" at -423,-1637.06 h60
M14 Component Bodies Bottom:
  text ".Layer_Name" at -423,-1637.06 h60
M15 Courtyards Top:
  text ".Layer_Name" at -423,-1637.06 h60
M16 Courtyards Bottom:
  text ".Layer_Name" at -423,-1637.06 h60
Drill Drawing:
  lines w8: -1243.55,3678.15 -1243.55,3796.86 -1116.65,3796.86 -1116.65,3678.15 -1243.55,3678.15 ; -1213.31,5928.53 -1086.41,5928.53 -1086.41,6047.24 -1213.31,6047.24 -1213.31,5928.53 ; -1213.31,6087.65 -1086.41,6087.65 -1086.41,6206.35 -1213.31,6206.35 -1213.31,6087.65 ; -1213.31,6261.38 -1086.41,6261.38 -1086.41,6380.08 -1213.31,6380.08 -1213.31,6261.38 ; -1213.31,6435.11 -1213.31,6553.81 -1086.41,6553.81 -1086.41,6435.11 -1213.31,6435.11
  lines w15: -1094.8,3658.52 4409.91,3658.52 ; -1094.8,3824.28 4409.91,3824.28 ; -1041.41,4761.67 4649.74,4761.67 ; -1041.41,6585.03 4649.74,6585.03 ; -644.32,3492.76 -644.32,3990.04 ; -590.92,4595.91 -590.92,6750.79 ; -165.78,3492.76 -165.78,3990.04 ; -112.38,4595.91 -112.38,6750.79 ; 682.97,3492.76 682.97,3990.04 ; 736.37,4595.91 736.37,6750.79 ; 1028.49,3492.76 1028.49,3990.04 ; 1081.89,4595.91 1081.89,6750.79 ; 1528.7,3492.76 1528.7,3990.04 ; 1582.1,4595.91 1582.1,6750.79 ; 2274.89,3492.76 2274.89,3990.04 ; 2331.28,4595.91 2331.28,6750.79 ; 3078,3492.76 3078,3990.04 ; 3134.39,4595.91 3134.39,6750.79 ; 3860.33,3492.76 3860.33,3990.04 ; 4100.16,4595.91 4100.16,6750.79 ; -1094.8,3492.76 4409.91,3492.76 4409.91,3990.04 -1094.8,3990.04 -1094.8,3492.76 ; -1041.41,4595.91 4649.74,4595.91 4649.74,6750.79 -1041.41,6750.79 -1041.41,4595.91
  text "Drill Table: Top Layer to Bottom Layer" at -916.05,6789.11 h80
  text "Symbol" at -941.95,6634.76 h96
  text "Hit Count" at -541.2,6634.76 h96
  text "Finished Hole Size" at -62.65,6634.76 h96
  text "Plated" at 786.1,6634.76 h96
  text "Hole Type" at 1131.62,6634.76 h96
  text "Physical Length" at 1631.83,6634.76 h96
  text "Rout Path Length" at 2381.01,6634.76 h96
  text "Drill Layer Pair" at 3184.11,6634.76 h96
  text "Tolerance" at 4149.89,6634.76 h96
  text "16" at -541.2,6469 h80
  text "7.87mil (0.200mm)" at -62.65,6469 h80
  text "PTH" at 786.1,6469 h80
  text "Round" at 1131.62,6469 h80
  text "-" at 1631.83,6469 h80
  text "-" at 2381.01,6469 h80
  text "Top Layer - Bottom Layer" at 3184.11,6469 h80
  text "+0/-7.874mil" at 4149.89,6469 h80
  text "8" at -1176.31,6454.02 h80
  text "B" at -976.81,6454.01 h73.67
  text "71" at -541.2,6303.24 h80
  text "8.00mil (0.203mm)" at -62.65,6303.24 h80
  text "PTH" at 786.1,6303.24 h80
  text "Round" at 1131.62,6303.24 h80
  text "-" at 1631.83,6303.24 h80
  text "-" at 2381.01,6303.24 h80
  text "Top Layer - Bottom Layer" at 3184.11,6303.24 h80
  text "+0/-8mil" at 4149.89,6303.24 h80
  text "C" at -976.81,6288.25 h73.67
  text "8" at -1176.31,6280.29 h80
  text "566" at -541.2,6137.48 h80
  text "12.20mil (0.310mm)" at -62.65,6137.48 h80
  text "PTH" at 786.1,6137.48 h80
  text "Round" at 1131.62,6137.48 h80
  text "-" at 1631.83,6137.48 h80
  text "-" at 2381.01,6137.48 h80
  text "Top Layer - Bottom Layer" at 3184.11,6137.48 h80
  text "+0/-12.2mil" at 4149.89,6137.48 h80
  text "D" at -976.81,6122.49 h73.67
  text "8" at -1176.31,6106.57 h80
  text "28" at -541.2,5971.72 h80
  text "15.00mil (0.381mm)" at -62.65,5971.72 h80
  text "PTH" at 786.1,5971.72 h80
  text "Round" at 1131.62,5971.72 h80
  text "-" at 1631.83,5971.72 h80
  text "-" at 2381.01,5971.72 h80
  text "Top Layer - Bottom Layer" at 3184.11,5971.72 h80
  text "+0/-15mil" at 4149.89,5971.72 h80
  text "E" at -976.81,5956.73 h73.67
  text "8" at -1176.31,5947.45 h80
  text "6" at -541.2,5805.96 h80
  text "23.62mil (0.600mm)" at -62.65,5805.96 h80
  text "PTH" at 786.1,5805.96 h80
  text "Round" at 1131.62,5805.96 h80
  text "-" at 1631.83,5805.96 h80
  text "-" at 2381.01,5805.96 h80
  text "Top Layer - Bottom Layer" at 3184.11,5805.96 h80
  text "+/-3mil" at 4149.89,5805.96 h80
  text "G" at -976.81,5790.97 h73.67
  text "2" at -541.2,5640.2 h80
  text "23.62mil (0.600mm)" at -62.65,5640.2 h80
  text "PTH" at 786.1,5640.2 h80
  text "Slot" at 1131.62,5640.2 h80
  text "51.18mil (1.300mm)" at 1631.83,5640.2 h80
  text "27.56mil (0.700mm)" at 2381.01,5640.2 h80
  text "Top Layer - Bottom Layer" at 3184.11,5640.2 h80
  text "+/-3mil" at 4149.89,5640.2 h80
  text "F" at -976.81,5625.21 h73.67
  text "2" at -541.2,5474.44 h80
  text "33.47mil (0.850mm)" at -62.65,5474.44 h80
  text "PTH" at 786.1,5474.44 h80
  text "Round" at 1131.62,5474.44 h80
  text "-" at 1631.83,5474.44 h80
  text "-" at 2381.01,5474.44 h80
  text "Top Layer - Bottom Layer" at 3184.11,5474.44 h80
  text "+/-3mil" at 4149.89,5474.44 h80
  text "H" at -976.81,5459.45 h73.67
  text "4" at -541.2,5308.68 h80
  text "40.00mil (1.016mm)" at -62.65,5308.68 h80
  text "PTH" at 786.1,5308.68 h80
  text "Round" at 1131.62,5308.68 h80
  text "-" at 1631.83,5308.68 h80
  text "-" at 2381.01,5308.68 h80
  text "Top Layer - Bottom Layer" at 3184.11,5308.68 h80
  text "+/-3mil" at 4149.89,5308.68 h80
  text "I" at -964.54,5293.69 h73.67
  text "6" at -541.2,5142.92 h80
  text "40.16mil (1.020mm)" at -62.65,5142.92 h80
  text "NPTH" at 786.1,5142.92 h80
  text "Round" at 1131.62,5142.92 h80
  text "-" at 1631.83,5142.92 h80
  text "-" at 2381.01,5142.92 h80
  text "Top Layer - Bottom Layer" at 3184.11,5142.92 h80
  text "+/-2mil" at 4149.89,5142.92 h80
  text "J" at -976.81,5127.93 h73.67
  text "1" at -541.2,4977.16 h80
  text "80.00mil (2.032mm)" at -62.65,4977.16 h80
  text "PTH" at 786.1,4977.16 h80
  text "Round" at 1131.62,4977.16 h80
  text "-" at 1631.83,4977.16 h80
  text "-" at 2381.01,4977.16 h80
  text "Top Layer - Bottom Layer" at 3184.11,4977.16 h80
  text "+/-3mil" at 4149.89,4977.16 h80
  text "K" at -976.81,4962.17 h73.67
  text "8" at -541.2,4811.4 h80
  text "118.11mil (3.000mm)" at -62.65,4811.4 h80
  text "PTH" at 786.1,4811.4 h80
  text "Round" at 1131.62,4811.4 h80
  text "-" at 1631.83,4811.4 h80
  text "-" at 2381.01,4811.4 h80
  text "Top Layer - Bottom Layer" at 3184.11,4811.4 h80
  text "+/-3mil" at 4149.89,4811.4 h80
  text "L" at -976.81,4796.41 h73.67
  text "710 Total" at -541.2,4645.64 h80
  text "Slot definitions :" at -941.95,4529.61 h80
  text "Rout Path Length" at -341,4529.61 h80
  text "= Calculated from tool start centre position to tool end centre position." at 295.11,4529.61 h80
  text "Physical Length" at -341,4463.3 h80
  text "= Rout Path Length + Tool Size = Slot length as defined in the PCB layout" at 247.67,4463.3 h80
  text "Drill Table: Layer 1 To Layer 2" at -1089.09,4022.94 h80
  text "Symbol" at -995.35,3874 h96
  text "Hit Count" at -594.59,3874 h96
  text "Finished Hole Size" at -116.05,3874 h96
  text "Plated" at 732.7,3874 h96
  text "Hole Type" at 1078.22,3874 h96
  text "Physical Length" at 1578.43,3874 h96
  text "Rout Path Length" at 2324.62,3874 h96
  text "Drill Layer Pair" at 3127.73,3874 h96
  text "Tolerance" at 3910.05,3874 h96
  text "988" at -594.59,3708.24 h80
  text "5.90mil (0.150mm)" at -116.05,3708.24 h80
  text "PTH" at 732.7,3708.24 h80
  text "Round" at 1078.22,3708.24 h80
  text "-" at 1578.43,3708.24 h80
  text "-" at 2324.62,3708.24 h80
  text "Top Layer - L2_GND" at 3127.73,3708.24 h80
  text "+0/-5.9mil" at 3910.05,3708.24 h80
  text "8" at -1206.55,3697.07 h80
  text "A" at -1030.21,3693.26 h73.67
  text "988 Total" at -594.59,3542.48 h80
  text ".Layer_Name" at -423,-1637.06 h60
M17 Embedded Cavity:
  text ".Layer_Name" at -423,-1637.06 h60
M18 Embedded Assembly:
  text ".Layer_Name" at -423,-1637.06 h60
M19 Embedded Keepout:
  text ".Layer_Name" at -423,-1637.06 h60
